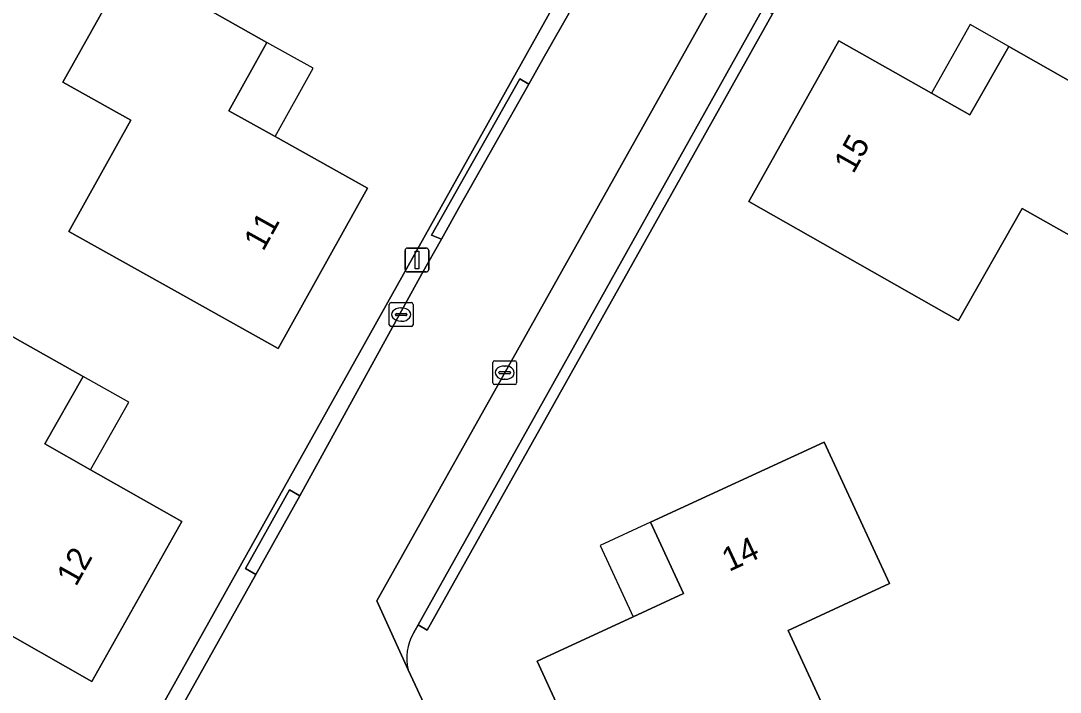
# Model space of a CAD drawing. Extents: x 163266 to 164362, y 381528 to 382286.
# Drawn here: x 163565.01 to 163608.69, y 381601.51 to 381629.72 of the extents above; entities that cross this region are included whole.
import ezdxf

# ---------------------------------------------------------------- set-up
doc = ezdxf.new("R2010")
doc.units = 0
for name, color, linetype in [('IMGEO_Erf', 7, 'Continuous'), ('IMGEO_Kolk', 7, 'Continuous'), ('IMGEO_Lichtmast', 7, 'Continuous'), ('IMGEO_Pand', 7, 'Continuous'), ('IMGEO_Pand_nummerreeks', 7, 'Continuous'), ('IMGEO_Pand_overbouw', 7, 'Continuous'), ('IMGEO_Parkeervlak_open', 7, 'Continuous'), ('IMGEO_Rijbaan_lokaal_open', 7, 'Continuous'), ('IMGEO_Voetpad_open', 7, 'Continuous')]:
    doc.layers.add(name, color=color, linetype=linetype)

msp = doc.modelspace()

# ---------------------------------------------------------------- linework, layer by layer
at = {"layer": 'IMGEO_Erf'}
for points in [[(163568.157, 381595.963), (163603.714, 381659.518)], [(163608.001, 381655.317), (163597.502, 381636.602), (163599.222, 381635.625), (163598.049, 381633.549), (163598.442, 381633.306), (163596.599, 381630.014), (163582.081, 381604.121), (163581.708, 381604.343), (163581.508, 381603.985)], [(163581.284, 381602.447), (163586.783, 381590.674), (163589.374, 381591.224), (163593.379, 381593.084), (163622.355, 381606.539), (163623.496, 381604.168), (163677.889, 381629.916), (163692.948, 381637.102), (163693.217, 381637.23), (163693.201, 381637.598), (163686.863, 381639.858), (163679.05, 381642.678), (163675.489, 381643.937), (163670.794, 381645.621), (163667.214, 381646.884), (163653.06, 381651.93)]]:
    msp.add_lwpolyline(points, dxfattribs=at)
for points in [[(163575.826, 381615.945), (163571.462, 381618.383), (163567.023, 381620.863), (163569.637, 381625.544), (163566.777, 381627.141), (163569.528, 381632.064), (163572.937, 381630.161), (163575.355, 381628.81), (163573.753, 381625.942), (163575.7, 381624.855), (163579.574, 381622.692)], [(163609.944, 381620.221), (163607.086, 381621.84), (163604.418, 381617.132), (163595.599, 381622.127), (163599.389, 381628.882), (163603.274, 381626.682), (163604.893, 381625.765), (163606.523, 381628.642), (163612.724, 381625.131)], [(163571.774, 381608.689), (163567.998, 381601.96), (163563.647, 381604.423), (163559.259, 381606.906), (163561.905, 381611.581), (163559.071, 381613.185), (163559.466, 381613.951), (163558.574, 381614.411), (163558.077, 381613.447), (163550.814, 381617.191), (163553.88, 381622.554), (163561.638, 381618.165), (163561.827, 381618.058), (163565.194, 381616.153), (163567.627, 381614.776), (163566.023, 381611.942), (163567.941, 381610.857)], [(163601.513, 381606.072), (163597.254, 381604.107), (163599.143, 381600.019), (163589.944, 381595.773), (163586.707, 381602.82), (163590.74, 381604.683), (163592.854, 381605.659), (163591.473, 381608.649), (163598.767, 381612.017)]]:
    msp.add_lwpolyline(points, close=True, dxfattribs=at)
msp.add_arc((163583.335, 381602.934), 2.108, 150.078, 193.349, dxfattribs=at)
at = {"layer": 'IMGEO_Kolk'}
for p, q in [((163580.494, 381616.951), (163580.494, 381617.803)), ((163580.569, 381617.877), (163581.421, 381617.877)), ((163581.495, 381617.803), (163581.495, 381616.951)), ((163580.753, 381617.371), (163580.753, 381617.383)), ((163580.796, 381617.42), (163581.194, 381617.42)), ((163580.982, 381617.657), (163581.007, 381617.657)), ((163581.237, 381617.383), (163581.237, 381617.371)), ((163581.191, 381617.334), (163580.793, 381617.334)), ((163581.005, 381617.097), (163580.98, 381617.097)), ((163581.421, 381616.877), (163580.569, 381616.877)), ((163584.845, 381614.51), (163584.845, 381615.362)), ((163584.92, 381615.436), (163585.772, 381615.436)), ((163585.333, 381615.216), (163585.358, 381615.216)), ((163585.846, 381615.362), (163585.846, 381614.51)), ((163585.104, 381614.93), (163585.104, 381614.942)), ((163585.542, 381614.893), (163585.144, 381614.893)), ((163585.147, 381614.979), (163585.545, 381614.979)), ((163585.588, 381614.942), (163585.588, 381614.93)), ((163585.772, 381614.436), (163584.92, 381614.436)), ((163585.356, 381614.656), (163585.331, 381614.656))]:
    msp.add_line(p, q, dxfattribs=at)
for points in [[(163580.494, 381616.951), (163580.494, 381617.803)], [(163580.569, 381617.877), (163581.421, 381617.877)], [(163581.495, 381617.803), (163581.495, 381616.951)], [(163581.421, 381616.877), (163580.569, 381616.877)], [(163584.845, 381614.51), (163584.845, 381615.362)], [(163584.92, 381615.436), (163585.772, 381615.436)], [(163585.846, 381615.362), (163585.846, 381614.51)], [(163585.772, 381614.436), (163584.92, 381614.436)]]:
    msp.add_lwpolyline(points, dxfattribs=at)
for centre, radius, start, end in [((163580.571, 381617.801), 0.0765, 91.552, 178.448), ((163580.571, 381617.801), 0.0765, 91.552, 178.448), ((163581.419, 381617.801), 0.0765, 1.552, 88.448), ((163581.419, 381617.801), 0.0765, 1.552, 88.448), ((163580.793, 381617.38), 0.0403, 85.8775, 175.7526), ((163580.79, 381617.37), 0.0366, 178.938, 274.7102), ((163581.194, 381617.377), 0.043, 264.8664, 352.4533), ((163581.198, 381617.382), 0.0386, 1.7309, 96.639), ((163580.571, 381616.953), 0.0765, 181.552, 268.448), ((163580.571, 381616.953), 0.0765, 181.552, 268.448), ((163581.419, 381616.953), 0.0765, 271.552, 358.448), ((163581.419, 381616.953), 0.0765, 271.552, 358.448), ((163584.922, 381615.36), 0.0765, 91.552, 178.448), ((163584.922, 381615.36), 0.0765, 91.552, 178.448), ((163585.77, 381615.36), 0.0765, 1.552, 88.448), ((163585.77, 381615.36), 0.0765, 1.552, 88.448), ((163585.144, 381614.939), 0.0403, 85.8775, 175.7526), ((163585.141, 381614.929), 0.0366, 178.938, 274.7102), ((163585.545, 381614.936), 0.043, 264.8664, 352.4533), ((163585.549, 381614.941), 0.0386, 1.7309, 96.639), ((163584.922, 381614.512), 0.0765, 181.552, 268.448), ((163584.922, 381614.512), 0.0765, 181.552, 268.448), ((163585.77, 381614.512), 0.0765, 271.552, 358.448), ((163585.77, 381614.512), 0.0765, 271.552, 358.448)]:
    msp.add_arc(centre, radius, start, end, dxfattribs=at)
for centre, major_axis, ratio, start_param, end_param in [((163580.981, 381617.377), (-0.387, 0.002), 0.722429, 4.712389, 7.853982), ((163581.006, 381617.377), (-0.39, 0.002), 0.717154, 1.570796, 4.712389), ((163585.332, 381614.936), (-0.387, 0.002), 0.722429, 4.712389, 7.853982), ((163585.357, 381614.936), (-0.39, 0.002), 0.717154, 1.570796, 4.712389)]:
    msp.add_ellipse(centre, major_axis=major_axis, ratio=ratio, start_param=start_param, end_param=end_param, dxfattribs=at)
at = {"layer": 'IMGEO_Lichtmast'}
for p, q in [((163581.159, 381619.269), (163581.159, 381620.069)), ((163581.159, 381620.069), (163581.159, 381619.269)), ((163581.259, 381620.169), (163582.049, 381620.169)), ((163582.049, 381620.169), (163581.259, 381620.169)), ((163582.149, 381620.069), (163582.149, 381619.269)), ((163582.149, 381619.269), (163582.149, 381620.069)), ((163582.049, 381619.169), (163581.259, 381619.169)), ((163581.259, 381619.169), (163582.049, 381619.169))]:
    msp.add_line(p, q, dxfattribs=at)
msp.add_lwpolyline([(163581.579, 381620.044), (163581.729, 381620.044), (163581.729, 381619.294), (163581.579, 381619.294), (163581.579, 381620.044)], dxfattribs=at)
for centre, start, end in [((163581.259, 381620.069), 90, 180), ((163581.259, 381620.069), 90, 180), ((163582.049, 381620.069), 0, 90), ((163582.049, 381620.069), 360, 90), ((163581.259, 381619.269), 180, 270), ((163581.259, 381619.269), 180, 270), ((163582.049, 381619.269), 270, 0), ((163582.049, 381619.269), 270, 0)]:
    msp.add_arc(centre, 0.1, start, end, dxfattribs=at)
at = {"layer": 'IMGEO_Pand'}
for points in [[(163575.7, 381624.855), (163573.753, 381625.942), (163575.355, 381628.81), (163572.937, 381630.161), (163569.528, 381632.064), (163566.777, 381627.141), (163569.637, 381625.544), (163567.023, 381620.863), (163571.462, 381618.383), (163575.826, 381615.945), (163579.574, 381622.692)], [(163612.724, 381625.131), (163606.523, 381628.642), (163604.893, 381625.765), (163603.274, 381626.682), (163599.389, 381628.882), (163595.599, 381622.127), (163604.418, 381617.132), (163607.086, 381621.84), (163609.944, 381620.221)], [(163567.941, 381610.857), (163566.023, 381611.942), (163567.627, 381614.776), (163565.194, 381616.153), (163561.827, 381618.058), (163561.638, 381618.165), (163559.466, 381613.951), (163559.071, 381613.185), (163561.905, 381611.581), (163559.259, 381606.906), (163563.647, 381604.423), (163567.998, 381601.96), (163571.774, 381608.689)], [(163601.513, 381606.072), (163598.767, 381612.017), (163591.473, 381608.649), (163592.854, 381605.659), (163590.74, 381604.683), (163586.707, 381602.82), (163589.944, 381595.773), (163599.143, 381600.019), (163597.254, 381604.107)]]:
    msp.add_lwpolyline(points, close=True, dxfattribs=at)
at = {"layer": 'IMGEO_Pand_overbouw'}
for points in [[(163606.523, 381628.642), (163604.904, 381629.559), (163603.274, 381626.682), (163604.893, 381625.765)], [(163577.302, 381627.723), (163575.355, 381628.81), (163573.753, 381625.942), (163575.7, 381624.855)], [(163569.545, 381613.691), (163567.627, 381614.776), (163566.023, 381611.942), (163567.941, 381610.857)], [(163591.473, 381608.649), (163589.359, 381607.673), (163590.74, 381604.683), (163592.854, 381605.659)]]:
    msp.add_lwpolyline(points, close=True, dxfattribs=at)
at = {"layer": 'IMGEO_Parkeervlak_open'}
msp.add_lwpolyline([(163581.508, 381603.985), (163581.708, 381604.343), (163596.189, 381630.224), (163598.049, 381633.549), (163599.222, 381635.625), (163597.502, 381636.602), (163579.965, 381605.349), (163581.284, 381602.447)], dxfattribs=at)
msp.add_arc((163583.335, 381602.934), 2.108, 150.078, 193.349, dxfattribs=at)
at = {"layer": 'IMGEO_Rijbaan_lokaal_open'}
for points in [[(163606.225, 381661.643), (163604.442, 381659.245), (163600.3, 381651.858), (163598.448, 381648.55), (163592.355, 381637.666), (163590.507, 381634.364), (163586.954, 381628.141), (163586.355, 381627.06), (163583.478, 381621.954), (163582.682, 381620.541), (163581.862, 381619.092), (163576.737, 381609.767), (163574.885, 381606.46), (163569.075, 381596.081)], [(163568.675, 381586.379), (163570.211, 381583.162), (163570.401, 381582.765), (163582.919, 381588.471), (163585.659, 381589.713), (163586.942, 381590.334), (163586.783, 381590.674), (163581.284, 381602.447), (163579.965, 381605.349), (163597.502, 381636.602), (163608.001, 381655.317)]]:
    msp.add_lwpolyline(points, dxfattribs=at)
at = {"layer": 'IMGEO_Voetpad_open'}
for points in [[(163603.714, 381659.518), (163568.157, 381595.963)], [(163568.562, 381596.279), (163569.075, 381596.081), (163574.885, 381606.46), (163574.449, 381606.704), (163576.301, 381610.011), (163576.737, 381609.767), (163581.862, 381619.092), (163582.682, 381620.541), (163582.269, 381620.711), (163585.975, 381627.286), (163586.355, 381627.06), (163586.954, 381628.141), (163590.507, 381634.364)]]:
    msp.add_lwpolyline(points, dxfattribs=at)
for points in [[(163596.189, 381630.224), (163581.708, 381604.343), (163582.081, 381604.121), (163596.599, 381630.014)], [(163586.355, 381627.06), (163585.975, 381627.286), (163582.269, 381620.711), (163582.682, 381620.541), (163583.478, 381621.954)], [(163576.737, 381609.767), (163576.301, 381610.011), (163574.449, 381606.704), (163574.885, 381606.46)]]:
    msp.add_lwpolyline(points, close=True, dxfattribs=at)

# ---------------------------------------------------------------- texts
at = {"layer": 'IMGEO_Pand_nummerreeks'}
for s, rotation, p in [('15', 60.7049, (163599.994, 381623.258)), ('11', 60.9455, (163575.195, 381620)), ('14', 24.7862, (163594.771, 381606.559)), ('12', 60.6991, (163567.327, 381605.915))]:
    msp.add_text(s, height=1, rotation=rotation, dxfattribs=at).set_placement(p)

doc.saveas('drawing.dxf')
